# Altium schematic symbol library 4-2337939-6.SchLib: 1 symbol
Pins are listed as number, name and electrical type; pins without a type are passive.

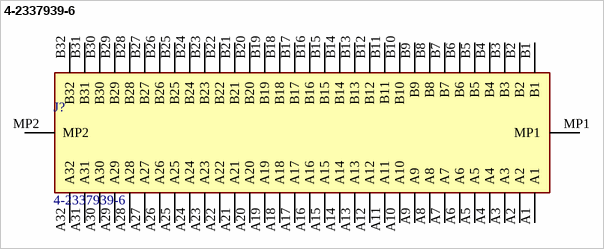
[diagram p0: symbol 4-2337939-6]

## 4-2337939-6
designator J?
PCIE GEN4 CON,SMT,64POS,15u",MYLAR,ST; Manufacturer_Name: TE Connectivity; Geometry.Height: 11.25mm
footprint 423379396
pins: A1, A2, A3, A4, A5, A6, A7, A8, A9, A10, A11, A12, A13, A14, A15, A16, A17, A18, A19, A20, A21, A22, A23, A24, A25, A26, A27, A28, A29, A30, A31, A32, B1, B2, B3, B4, B5, B6, B7, B8, B9, B10, B11, B12, B13, B14, B15, B16, B17, B18, B19, B20, B21, B22, B23, B24, B25, B26, B27, B28, B29, B30, B31, B32, MP1, MP2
